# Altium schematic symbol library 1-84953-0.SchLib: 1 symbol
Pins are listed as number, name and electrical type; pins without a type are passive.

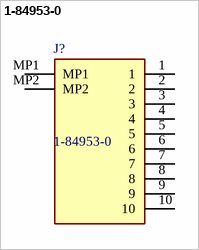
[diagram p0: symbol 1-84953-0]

## 1-84953-0
designator J?
10 way r/a top FFC SMT connector,1mm; Manufacturer_Name: TE Connectivity; Geometry.Height: 2.74mm
footprint 1849530
pins: 1, 2, 3, 4, 5, 6, 7, 8, 9, 10, MP1, MP2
